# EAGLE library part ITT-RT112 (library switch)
ROTARY SWITCH ITT-Cannon
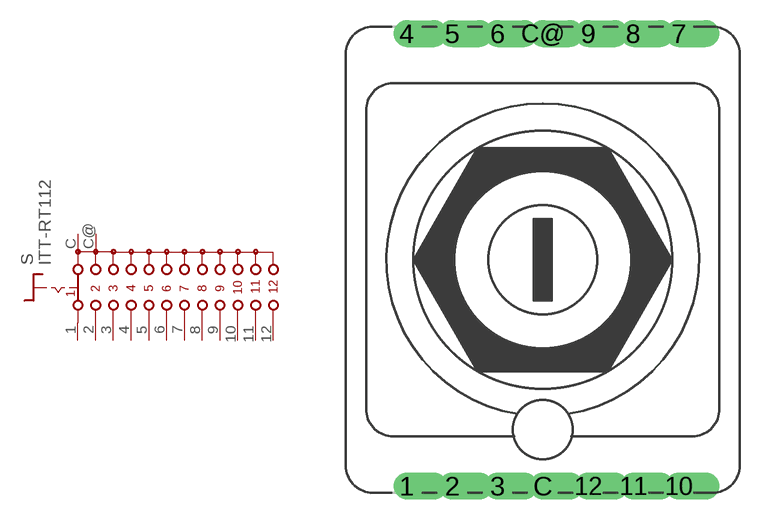
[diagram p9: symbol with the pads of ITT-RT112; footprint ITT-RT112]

Designator prefix S

## ITT-RT112  [ITT-RT112]
1  1  pas
2  2  pas
3  3  pas
4  4  pas
5  5  pas
6  6  pas
7  7  pas
8  8  pas
9  9  pas
10  10  pas
11  11  pas
12  12  pas
C  C  pas
C@  C  pas

## Footprint ITT-RT112 (pad centres in mm)
ROTARY SWITCH ITT-Cannon
drill 1.016 offset: 1 -7.62,-12.7; 2 -5.08,-12.7; 3 -2.54,-12.7; 4 -7.62,12.7; 5 -5.08,12.7; 6 -2.54,12.7; 7 7.62,12.7; 8 5.08,12.7; 9 2.54,12.7; 10 7.62,-12.7; 11 5.08,-12.7; 12 2.54,-12.7; C 0,-12.7; C@ 0,12.7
